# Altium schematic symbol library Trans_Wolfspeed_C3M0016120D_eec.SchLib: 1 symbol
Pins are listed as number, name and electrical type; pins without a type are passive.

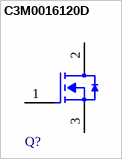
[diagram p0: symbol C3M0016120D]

## C3M0016120D
designator Q?  (value not drawn)
pins: 1 Gate, 2 Drain, 3 Source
